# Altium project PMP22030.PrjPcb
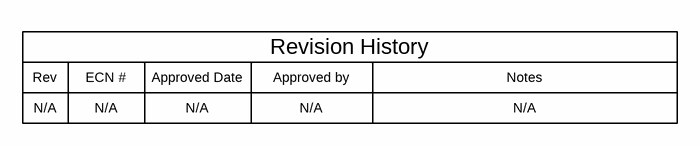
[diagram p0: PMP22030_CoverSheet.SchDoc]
CopyrightYear: 2019; PCB_Layout: Dee Lim; PCB_Rev: E1; PRJ_Customer: Public Release; PRJ_Engineer: Pradeep Shenoy; PRJ_Number: PMP22030; PRJ_Title: Automotive Infotainment Display; SCH_Rev: E1; TechSupport: http://www.ti.com/support; TID: N/A
4 sheets, 126 parts. Net scope: global (net labels, ports and power ports of the same name join across sheets).
Board file: PMP22030_PCB.PcbDoc
Sheets:
  PMP22030_CoverSheet.SchDoc
  PMP22030_Hardware.SchDoc
  PMP22030_3V3.SchDoc
  PMP22030_5V.SchDoc

## Sheet PMP22030_CoverSheet.SchDoc
size 431 x 279 mm; Date: Not shown in title block; ApprovedBy: Not shown in title block; CheckedBy: Not shown in title block; Author: Not shown in title block; CompanyName: Not shown in title block; Engineer: Not shown in title block; Organization: Not shown in title block; Address1: Not shown in title block; Address2: Not shown in title block; Address3: Not shown in title block; Address4: Not shown in title block; DocumentNumber: 1; Revision: Use project parameter SCH_Rev; SheetNumber: 1; SheetTotal: 4; PageSetup: Record=PageOptions¦CenterHorizontal=True¦CenterVertical=True¦PrintScale=1.00¦XCorrection=1.00¦YCorrection=1.00¦PrintKind=0¦BorderSize=5000000¦LeftOffset=0¦BottomOffset=0¦Orientation=2¦PaperLength=1000¦PaperWidth=1000¦Scale=100¦PaperSource=15¦PrintQuality=600¦MediaType=1¦DitherType=10¦PaperKind=Letter¦PrintScaleMode=1

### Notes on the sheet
- Rev
- N/A
- ECN #
- Approved Date
- Approved by
- Revision History
- Notes

## Sheet PMP22030_Hardware.SchDoc
size 431 x 279 mm; Date: Not shown in title block; ApprovedBy: Not shown in title block; CheckedBy: Not shown in title block; Author: Not shown in title block; CompanyName: Not shown in title block; Engineer: Not shown in title block; Organization: Not shown in title block; Address1: Not shown in title block; Address2: Not shown in title block; Address3: Not shown in title block; Address4: Not shown in title block; DocumentNumber: 4; Revision: Use project parameter SCH_Rev; SheetNumber: 4; SheetTotal: 4; PageSetup: Record=PageOptions¦CenterHorizontal=True¦CenterVertical=True¦PrintScale=1.00¦XCorrection=1.00¦YCorrection=1.00¦PrintKind=0¦BorderSize=5000000¦LeftOffset=0¦BottomOffset=0¦Orientation=2¦PaperLength=1000¦PaperWidth=1000¦Scale=100¦PaperSource=15¦PrintQuality=600¦MediaType=1¦DitherType=10¦PaperKind=Letter¦PrintScaleMode=1
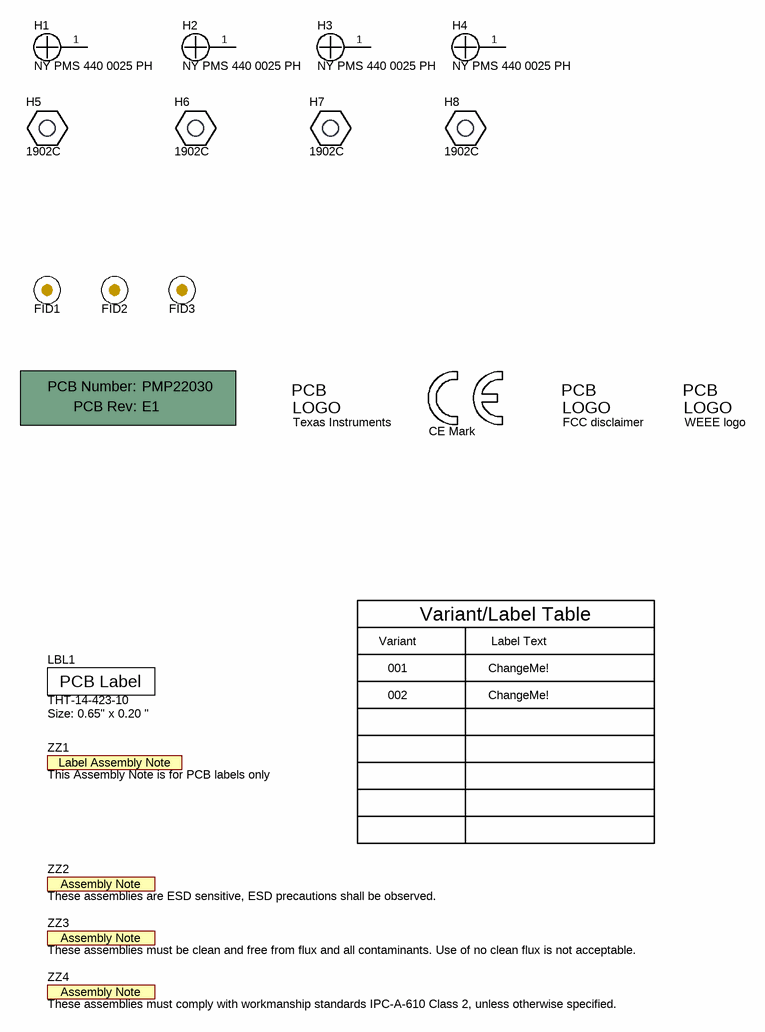
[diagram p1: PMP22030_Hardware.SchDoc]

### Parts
!PCB1  Printed Circuit Board  (value not drawn)  (mechanical)
FID1  Fiducial  [Fiducial10-20]  (value not drawn)
FID2  Fiducial  [Fiducial10-20]  (value not drawn)
FID3  Fiducial  [Fiducial10-20]  (value not drawn)
H1  NY PMS 440 0025 PH  [NY PMS 440 0025 PH]
H2  NY PMS 440 0025 PH  [NY PMS 440 0025 PH]
H3  NY PMS 440 0025 PH  [NY PMS 440 0025 PH]
H4  NY PMS 440 0025 PH  [NY PMS 440 0025 PH]
H5  1902C  [Keystone_1902C]
H6  1902C  [Keystone_1902C]
H7  1902C  [Keystone_1902C]
H8  1902C  [Keystone_1902C]
LBL1  THT-14-423-10  Note: Size: 0.65" x 0.20 "  [Label_650x200]
Logo1  CE Mark  [CE_Mark_5mm]  (no BOM)
Logo2  Texas Instruments  [TI_Stacked_Overlay_Small]  (no BOM)
Logo3  FCC disclaimer  [FCC_disclaimer]  (no BOM)
Logo4  WEEE logo  [WEEE_Minimum]  (no BOM)
ZZ1  This Assembly Note is for PCB labels only  [AssemblyNoteLabel]  (no BOM)
ZZ2  These assemblies are ESD sensitive, ESD precautions shall be observed.  [AssemblyNote]  (no BOM)
ZZ3  These assemblies must be clean and free from flux and all contaminants. Use of no clean flux is not acceptable.  [AssemblyNote]  (no BOM)
ZZ4  These assemblies must comply with workmanship standards IPC-A-610 Class 2, unless otherwise specified.  [AssemblyNote]  (no BOM)

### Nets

Not connected (* = marked no-connect by the designer): H1 1; H2 1; H3 1; H4 1

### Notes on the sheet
- Variant
- Variant/Label Table
- Label Text
- 001
- 002
- ChangeMe!

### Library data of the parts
!PCB1 = CMP-0003618-2: Manufacturer: Any; PartNumber: PMP22030
FID1-FID3 = CMP-0077181-1: Fiducial mark.  There is nothing to buy or mount.
H1-H4 = CMP-0003617-1: Machine Screw, Round, #4-40 x 1/4, Nylon, Philips panhead; Manufacturer: B&F Fastener Supply; CompType: Hardware
H5-H8 = CMP-0003610-1: Standoff, Hex, 0.5"L #4-40 Nylon; Manufacturer: Keystone; CompType: Hardware
LBL1 = CMP-0003625-1: Thermal Transfer Printable Labels, 0.650" W x 0.200" H - 10,000 per roll; Manufacturer: Brady; CompType: Label
Logo1 = CMP-0074844-1: SymbolCreator: a0412235
Logo2 = CMP-0074838-1: Texas Instrument Corporate Signature; SymbolCreator: a0412235; Lib Reference: TI_Logo; Library Reference: Logo
Logo3 = CMP-0074847-1: FCC_disclaimer; Library Reference: Logo
Logo4 = CMP-0074769-1
ZZ1 = CMP-0003616-3
ZZ2 = CMP-0077236-1
ZZ3 = CMP-0077237-1
ZZ4 = CMP-0077238-1

## Sheet PMP22030_3V3.SchDoc
size 431 x 279 mm; Date: Not shown in title block; ApprovedBy: Not shown in title block; CheckedBy: Not shown in title block; Author: Not shown in title block; CompanyName: Not shown in title block; Engineer: Not shown in title block; Organization: Not shown in title block; Address1: Not shown in title block; Address2: Not shown in title block; Address3: Not shown in title block; Address4: Not shown in title block; DocumentNumber: 3; Revision: Use project parameter SCH_Rev; SheetNumber: 3; SheetTotal: 4; PageSetup: Record=PageOptions¦CenterHorizontal=True¦CenterVertical=True¦PrintScale=1.00¦XCorrection=1.00¦YCorrection=1.00¦PrintKind=0¦BorderSize=5000000¦LeftOffset=0¦BottomOffset=0¦Orientation=2¦PaperLength=1000¦PaperWidth=1000¦Scale=100¦PaperSource=15¦PrintQuality=600¦MediaType=1¦DitherType=10¦PaperKind=Letter¦PrintScaleMode=1
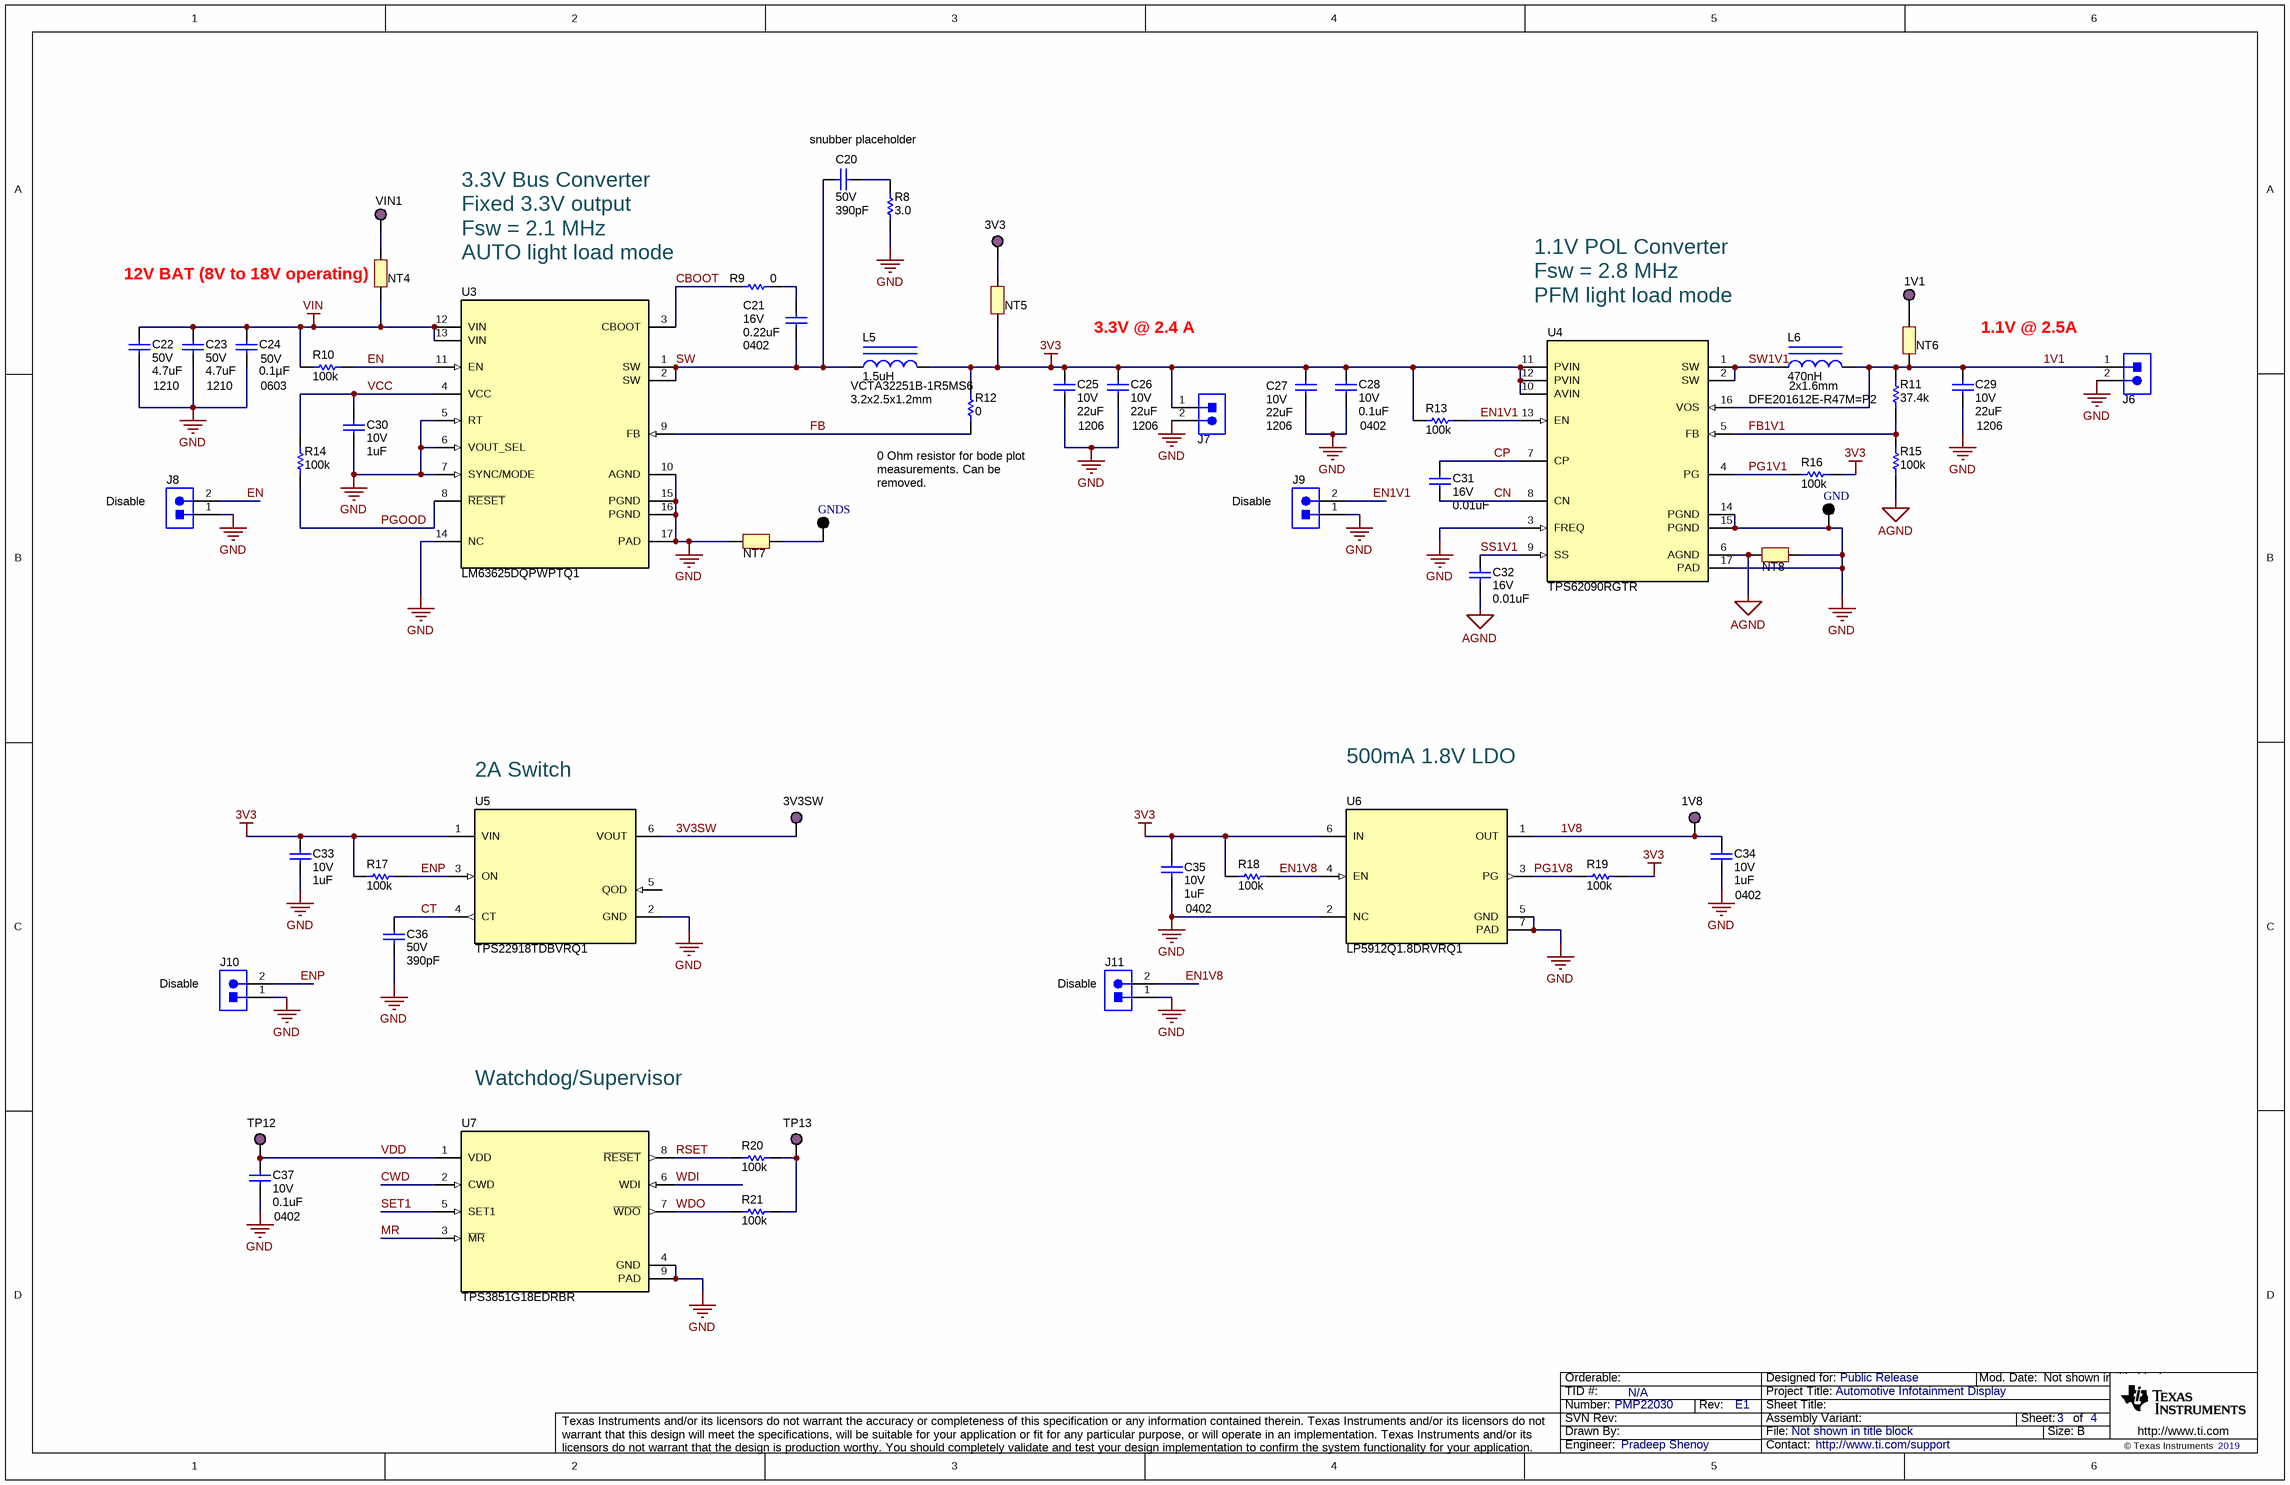
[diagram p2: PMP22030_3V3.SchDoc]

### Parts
1V1  5129  [Keystone5129]  (value not drawn)
1V8  5129  [Keystone5129]  (value not drawn)
3V3  5129  [Keystone5129]  (value not drawn)
3V3SW  5129  [Keystone5129]  (value not drawn)
C20  VDC_V: 50V  ValueDisplayed: 390pF  [0402S]  (hidden comment: GCM155R71H391KA37D)
C21  PackageReference: 0402  VDC_V: 16V  ValueDisplayed: 0.22uF  [0402S]  (hidden comment: C1005X7R1C224K050BC)
C22  PackageReference: 1210  VDC_V: 50V  ValueDisplayed: 4.7uF  [1210_280]  (hidden comment: CGA6P3X7R1H475K250AB)
C23  PackageReference: 1210  VDC_V: 50V  ValueDisplayed: 4.7uF  [1210_280]  (hidden comment: CGA6P3X7R1H475K250AB)
C24  Value2: 50V  ValueDisplayed: 0.1µF  [0603]  (hidden comment: CINHF)
C25  PackageReference: 1206  VDC_V: 10V  ValueDisplayed: 22uF  [1206_180]  (hidden comment: GCM31CR71A226KE02)
C26  PackageReference: 1206  VDC_V: 10V  ValueDisplayed: 22uF  [1206_180]  (hidden comment: GCM31CR71A226KE02)
C27  PackageReference: 1206  VDC_V: 10V  ValueDisplayed: 22uF  [1206_180]  (hidden comment: GCM31CR71A226KE02)
C28  VDC_V: 10V  ValueDisplayed: 0.1uF  [0402]  (hidden comment: GCM155R71A104KA55D)
C29  PackageReference: 1206  VDC_V: 10V  ValueDisplayed: 22uF  [1206_180]  (hidden comment: GCM31CR71A226KE02)
C30  VDC_V: 10V  ValueDisplayed: 1uF  [0402_070]  (hidden comment: GCM155C71A105KE38D)
C31  VDC_V: 16V  ValueDisplayed: 0.01uF  [0402S]  (hidden comment: GRM155R71C103KA01D)
C32  VDC_V: 16V  ValueDisplayed: 0.01uF  [0402S]  (hidden comment: GRM155R71C103KA01D)
C33  VDC_V: 10V  ValueDisplayed: 1uF  [0402_070]  (hidden comment: GCM155C71A105KE38D)
C34  PackageReference: 0402  VDC_V: 10V  ValueDisplayed: 1uF  [0402_070]  (hidden comment: GCM155C71A105KE38D)
C35  PackageReference: 0402  VDC_V: 10V  ValueDisplayed: 1uF  [0402_070]  (hidden comment: GCM155C71A105KE38D)
C36  VDC_V: 50V  ValueDisplayed: 390pF  [0402]  (hidden comment: GCM155R71H391KA37D)
C37  VDC_V: 10V  ValueDisplayed: 0.1uF  [0402]  (hidden comment: GCM155R71A104KA55D)
GND  5011  [Keystone5011]  (value not drawn)
GNDS  5011  [Keystone5011]  (value not drawn)
J6  PEC02SAAN  [CONN_PEC02SAAN]  (value not drawn)
J7  PEC02SAAN  [CONN_PEC02SAAN]  (value not drawn)
J8  PEC02SAAN  [CONN_PEC02SAAN]  (value not drawn)
J9  PEC02SAAN  [CONN_PEC02SAAN]  (value not drawn)
J10  PEC02SAAN  [CONN_PEC02SAAN]  (value not drawn)
J11  PEC02SAAN  [CONN_PEC02SAAN]  (value not drawn)
L5  PackageReference: 3.2x2.5x1.2mm  ValueDisplayed: 1.5uH  [VCTA32251B]  (hidden comment: VCTA32251B-1R5MS6)
L6  DFE201612E-R47M=P2  PackageReference: 2x1.6mm  ValueDisplayed: 470nH  [DFE201612E]
NT4  Net-Tie  [Net-Tie_10mil]  (value not drawn)  (net tie, no BOM)
NT5  Net-Tie  [Net-Tie_10mil]  (value not drawn)  (net tie, no BOM)
NT6  Net-Tie  [Net-Tie_10mil]  (value not drawn)  (net tie, no BOM)
NT7  Net-Tie  [Net-Tie_10mil]  (value not drawn)  (net tie, no BOM)
NT8  Net-Tie  [Net-Tie_10mil]  (value not drawn)  (net tie, no BOM)
R8  ValueDisplayed: 3.0  [0805]  (hidden comment: ERJ-6GEYJ3R0V)
R9  ValueDisplayed: 0  [0402S]  (hidden comment: CRCW04020000Z0EDHP)
R10  ValueDisplayed: 100k  [0402]  (hidden comment: RMCF0402FT100K)
R11  ValueDisplayed: 37.4k  [0402S]  (hidden comment: CRCW040237K4FKED)
R12  ValueDisplayed: 0  [0402]  (hidden comment: CRCW04020000Z0EDHP)
R13  ValueDisplayed: 100k  [0402]  (hidden comment: RMCF0402FT100K)
R14  ValueDisplayed: 100k  [0402]  (hidden comment: RMCF0402FT100K)
R15  ValueDisplayed: 100k  [0402S]  (hidden comment: CRCW0402100KFKED)
R16  ValueDisplayed: 100k  [0402]  (hidden comment: RMCF0402FT100K)
R17  ValueDisplayed: 100k  [0402]  (hidden comment: RMCF0402FT100K)
R18  ValueDisplayed: 100k  [0402]  (hidden comment: RMCF0402FT100K)
R19  ValueDisplayed: 100k  [0402]  (hidden comment: RMCF0402FT100K)
R20  ValueDisplayed: 100k  [0402]  (hidden comment: RMCF0402FT100K)
R21  ValueDisplayed: 100k  [0402]  (hidden comment: RMCF0402FT100K)
TP12  5129  [Keystone5129]  (value not drawn)
TP13  5129  [Keystone5129]  (value not drawn)
U3  LM63625DQPWPTQ1  [PWP0016K_N]
U4  TPS62090RGTR  [RGT0016C]
U5  TPS22918TDBVRQ1  [DBV0006A_N]
U6  LP5912Q1.8DRVRQ1  [DRV0006A]
U7  TPS3851G18EDRBR  [DRB0008A]
VIN1  5129  [Keystone5129]  (value not drawn)

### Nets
3V3: C25.1 C26.1 C27.1 C28.1 C33.1 C35.1 J7.1 L5.2 NT5.1 R12.1 R13.1 R16.2 R17.1 R18.1 R19.2 U4.10(AVIN) U4.11(PVIN) U4.12(PVIN) U5.1(VIN) U6.6(IN)
AGND: C32.2 NT8.2 R15.1 U4.6(AGND)
GND: C22.2 C23.2 C24.2 C25.2 C26.2 C27.2 C28.2 C29.2 C30.2 C33.2 C34.2 C35.2 C36.1 C37.2 GND.1 J6.2 J7.2 J8.1 J9.1 J10.1 J11.1 NT7.2 NT8.1 R8.1 U3.5(RT) U3.6(VOUT_SEL) U3.7(SYNC/MODE) U3.10(AGND) U3.14(NC) U3.15(PGND) U3.16(PGND) U3.17(PAD) U4.3(FREQ) U4.14(PGND) U4.15(PGND) U4.17(PAD) U5.2(GND) U6.2(NC) U6.5(GND) U6.7(PAD) U7.4(GND) U7.9(PAD)
VIN: C22.1 C23.1 C24.1 NT4.1 R10.1 U3.12(VIN) U3.13(VIN)
1V1: C29.1 J6.1 L6.2 NT6.1 R11.2 U4.16(VOS)
1V8: 1V8.1 C34.1 U6.1(OUT)
3V3SW: 3V3SW.1 U5.6(VOUT)
CBOOT: R9.2 U3.3(CBOOT)
CN: C31.2 U4.8(CN)
CP: C31.1 U4.7(CP)
CT: C36.2 U5.4(CT)
CWD: U7.2(CWD)
EN: J8.2 R10.2 U3.11(EN)
EN1V1: J9.2 R13.2 U4.13(EN)
EN1V8: J11.2 R18.2 U6.4(EN)
ENP: J10.2 R17.2 U5.3(ON)
FB: R12.2 U3.9(FB)
FB1V1: R11.1 R15.2 U4.5(FB)
MR: U7.3(~{MR})
PG1V1: R16.1 U4.4(PG)
PG1V8: R19.1 U6.3(PG)
PGOOD: R14.2 U3.8(~{RESET})
RSET: R20.1 U7.8(~{RESET})
SET1: U7.5(SET1)
SS1V1: C32.1 U4.9(SS)
SW: C20.2 C21.2 L5.1 U3.1(SW) U3.2(SW)
SW1V1: L6.1 U4.1(SW) U4.2(SW)
VCC: C30.1 R14.1 U3.4(VCC)
VDD: C37.1 TP12.1 U7.1(VDD)
WDI: U7.6(WDI)
WDO: R21.1 U7.7(~{WDO})
Net1V1_1: 1V1.1 NT6.2
Net3V3_1: 3V3.1 NT5.2
NetC20_1: C20.1 R8.2
NetC21_1: C21.1 R9.1
NetGNDS_1: GNDS.1 NT7.1
NetNT4_2: NT4.2 VIN1.1
NetR20_2: R20.2 R21.2 TP13.1

Not connected (* = marked no-connect by the designer): U5 5(QOD)

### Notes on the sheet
- snubber placeholder
- (near NT4) 12V BAT (8V to 18V operating)
- 3.3V Bus Converter
  Fixed 3.3V output
  Fsw = 2.1 MHz
  AUTO light load mode
- 3.3V @ 2.4 A
- 1.1V POL Converter
  Fsw = 2.8 MHz
  PFM light load mode
- 1.1V @ 2.5A
- (near J8) Disable
- (near R12) 0 Ohm resistor for bode plot measurements. Can be removed.
- (near J9) Disable
- (near U5) 2A Switch
- 500mA 1.8V LDO
- (near J10) Disable
- (near J11) Disable
- Watchdog/Supervisor

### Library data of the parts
1V1 1V8 3V3 3V3SW TP12 TP13 VIN1 = CMP-0055160-1: Test Point, Multipurpose, Purple, TH; Manufacturer: Keystone; CNHeader: FALSE; ContactFinish: Silver; CT: TRUE
C20 = CMP-0080703-2: CAP, CERM, 390 pF, 50 V,+/- 10%, X7R, AEC-Q200 Grade 1, 0402; Manufacturer: MuRata; Cap_Case: 0402; SizeX_mm: 1; SizeZ_mm: 0.6; SizeY_mm: 0.5; AEC Qualified: Y; Value: 390pF; Polarized: N; AEC Category: Q200; TaMax_C: 125°C; TaMin_C: -55°C; SizeAreaWB_mm2: 3; U/M: EA
C21 = CMP-0006293-1: CAP, CERM, 0.22 uF, 16 V, +/- 10%, X7R, 0402; Manufacturer: TDK; TaMin_C: -55°C; Polarized: N; SizeAreaWB_mm2: 3; Value1: Unknown; U/M: EA; Value: 0.22uF; TaMax_C: 125°C; SizeZ_mm: 0.6; SizeX_mm: 1; SizeY_mm: 0.5; Cap_F: 220nF; AEC Category: Q200
C22 C23 = CMP-0009162-2: CAP, CERM, 4.7 uF, 50 V, +/- 10%, X7R, AEC-Q200 Grade 1, 1210; Manufacturer: TDK; TaMin_C: -55°C; ESR_ohm: 3.166m; Polarized: N; SizeAreaWB_mm2: 14.7; Value1: 0.003166 ohm; U/M: EA; Value: 4.7uF; TaMax_C: 125°C; SizeZ_mm: 2.8; SizeX_mm: 3.2; SizeY_mm: 2.5; SizeArea_mm2: 8; AEC Qualified: Y; Cap_F: 4.7µF; IRMS_A: 4.13311A; AEC Grade: 1; AEC Category: Q200
C24 = CMP-0079602-1: CAP, CERM, 0.1 µF, 50 V,+/- 10%, X7R, AEC-Q200 Grade 1, 0603; Manufacturer: Kemet; PartNumber: C0603C104K5RACAUTO; TaMin_C: -55°C; Polarized: N; SizeAreaWB_mm2: 4.68; U/M: EA; Value: 0.1uF; TaMax_C: 125°C; SizeZ_mm: 1; SizeX_mm: 1.6; SizeY_mm: 0.8; SizeArea_mm2: 1.28; CompType: Capacitor; AEC Qualified: Y; Cap_F: 100nF; AEC Category: Q200
C25-C27 C29 = CMP-0008811-1: CAP, CERM, 22 uF, 10 V, +/- 10%, X7R, AEC-Q200 Grade 1, 1206; Manufacturer: MuRata; TaMin_C: -55°C; Polarized: N; SizeAreaWB_mm2: 10.92; Value1: Unknown; U/M: EA; Value: 22uF; TaMax_C: 125°C; SizeZ_mm: 1.8; SizeX_mm: 3.2; SizeY_mm: 1.6; SizeArea_mm2: 5.12; AEC Qualified: Y; Cap_F: 22µF; AEC Grade: 1; AEC Category: Q200
C28 C37 = CMP-0006350-2: CAP, CERM, 0.1 uF, 10 V, +/- 10%, X7R, AEC-Q200 Grade 1, 0402; Manufacturer: MuRata; TaMin_C: -55°C; Polarized: N; SizeAreaWB_mm2: 3; Value1: Unknown; U/M: EA; Value: 0.1uF; TaMax_C: 125°C; SizeZ_mm: 0.6; SizeX_mm: 1; SizeY_mm: 0.5; AEC Qualified: Y; Cap_F: 100nF; AEC Category: Q200
C30 C33 = CMP-0006349-1: CAP, CERM, 1 uF, 10 V, +/- 10%, X7S, AEC-Q200 Grade 1, 0402; Manufacturer: MuRata; TaMin_C: -55°C; Polarized: N; SizeAreaWB_mm2: 3; Value1: Unknown; U/M: EA; Value: 1uF; TaMax_C: 125°C; SizeZ_mm: 0.7; SizeX_mm: 1; SizeY_mm: 0.5; Cap_Case: 0402; AEC Qualified: Y; Cap_F: 1µF; AEC Category: Q200
C31 C32 = CMP-0006639-2: CAP, CERM, 0.01 uF, 16 V, +/- 10%, X7R, 0402; Manufacturer: MuRata; TaMin_C: -55°C; Polarized: N; SizeAreaWB_mm2: 3; Value1: Unknown; U/M: EA; Value: 0.01uF; TaMax_C: 125°C; SizeZ_mm: 0.6; SizeX_mm: 1; SizeY_mm: 0.5; Cap_Case: 0402; Cap_F: 10nF; AEC Category: Q200
C34 C35 = CMP-0006349-1: CAP, CERM, 1 uF, 10 V, +/- 10%, X7S, AEC-Q200 Grade 1, 0402; Manufacturer: MuRata; TaMin_C: -55°C; Polarized: N; SizeAreaWB_mm2: 3; Value1: Unknown; U/M: EA; Value: 1uF; TaMax_C: 125°C; SizeZ_mm: 0.7; SizeX_mm: 1; SizeY_mm: 0.5; AEC Qualified: Y; Cap_F: 1µF; AEC Category: Q200
C36 = CMP-0080703-2: CAP, CERM, 390 pF, 50 V,+/- 10%, X7R, AEC-Q200 Grade 1, 0402; Manufacturer: MuRata; SizeX_mm: 1; SizeZ_mm: 0.6; SizeY_mm: 0.5; AEC Qualified: Y; Value: 390pF; Polarized: N; AEC Category: Q200; TaMax_C: 125°C; TaMin_C: -55°C; SizeAreaWB_mm2: 3; U/M: EA
GND GNDS = CMP-0055148-1: Test Point, Multipurpose, Black, TH; Manufacturer: Keystone; CNHeader: FALSE; Green_Lifecycle: Active; Green_REACh: Passed; ContactFinish: Silver; CT: TRUE
J6-J11 = CMP-0002337-1: Header, 100mil, 2x1, Tin, TH; Manufacturer: Sullins Connector Solutions; CNHeader: TRUE; Current_A: 3A; Green_Lifecycle: Not Set; Shrouded: N; Gender: Male; Green_REACh: Incomplete; Voltage_V: 1.8kV; Row_Count: 1; Pitch_mm: 2.54; CT: FALSE; Cert_UL: Y
L5 = CMP-0059972-1: Inductor, 1.5 uH, 3.1 A, 0.054 ohm, SMD; Manufacturer: Cyntec; Isat: 3.7A @ 30% inductance drop; Irms: 3.1A @ 40C rise; SizeAreaWB_mm2: 14.7; DCR_ohm: 0.054; Value: 1.5uH; Imax_A: 3.1A; SizeZ_mm: 1.2; SizeX_mm: 3.2; SizeY_mm: 2.5; SizeArea_mm2: 8; Ind_H: 1.5µH; AEC Qualified: N; AEC Category: Q200
L6 = CMP-0080779-1: Inductor, Shielded, Metal Composite, 470 nH, 4.5 A, 0.026 ohm, SMD; Manufacturer: MuRata; Isat: 5.5A @ 30% inductance drop; Irms: 4.5A @ 40C rise; SizeAreaWB_mm2: 7.8; DCR_ohm: 0.026; Value: 470nH; Imax_A: 4.5A; SizeZ_mm: 1.2; SizeX_mm: 2; SizeY_mm: 1.6; SizeArea_mm2: 3.2; AEC Qualified: N; AEC Category: Q200
NT4-NT8 = CMP-0078142-1: Single point connection between nets.
R8 = CMP-0020720-3: RES, 3.0, 5%, 0.125 W, AEC-Q200 Grade 0, 0805; Manufacturer: Panasonic; Power_W: 125mW; TempCo: 600 ppm/C; Value_Code: 3R00; Value: 3.0; EIA_Code: E24; Res_ohm: 3; SizeX_mm: 2; SizeY_mm: 1.25; SizeZ_mm: 1.45; Value2: 0.125W; SizeArea_mm2: 2.5; AEC Qualified: Y; VDC_V: 150V; AEC Category: Q200; AEC Grade: 0; SizeAreaWB_mm2: 6.75
R9 R12 = CMP-0081856-1: RES, 0, 0%, 0.2 W, AEC-Q200 Grade 0, 0402; Manufacturer: Vishay-Dale; SizeAreaWB_mm2: 3; SizeArea_mm2: 0.5; AEC Qualified: Y; AEC Category: Q200; Value: 0; SizeZ_mm: 0.6; Power_W: 200mW; VDC_V: 50V; Value2: 0.2W; SizeX_mm: 1
R10 R13 R14 R16-R21 = CMP-0026753-1: RES, 100 k, 1%, 0.063 W, AEC-Q200 Grade 0, 0402; Manufacturer: Stackpole Electronics Inc; Power_W: 63mW; TempCo: 100 ppm/C; U/M: EA; Value: 100k; EIA_Code: E96; SizeX_mm: 1; SizeY_mm: 0.5; SizeZ_mm: 0.6; Value2: 0.063W; AEC Qualified: Y; VDC_V: 50V; AEC Grade: 0; AEC Category: Q200
R11 = CMP-0026319-2: RES, 37.4 k, 1%, 0.063 W, AEC-Q200 Grade 0, 0402; Manufacturer: Vishay-Dale; Power_W: 63mW; TempCo: 100 ppm/C; Value_Code: 37k4; Value: 37.4k; EIA_Code: E96; SizeX_mm: 1; SizeY_mm: 0.5; SizeZ_mm: 0.6; Value2: 0.063W; AEC Qualified: Y; VDC_V: 50V; AEC Category: Q200; AEC Grade: 0
R15 = CMP-0025950-3: RES, 100 k, 1%, 0.063 W, AEC-Q200 Grade 0, 0402; Manufacturer: Vishay-Dale; Power_W: 63mW; TempCo: 100 ppm/C; Value: 100k; EIA_Code: E96; SizeX_mm: 1; SizeY_mm: 0.5; SizeZ_mm: 0.6; Value2: 0.063W; AEC Qualified: Y; VDC_V: 50V; AEC Category: Q200; AEC Grade: 0
U3 = CMP-0080080-4: 3.5-V to 36-V, 2.5-A Synchronous Step-Down Voltage Regulator with Spread Spectrum, PWP0016D (TSSOP-16); Alternate Manufacturer: Texas Instruments; SizeAreaWB_mm2: 58.8; SizeZ_mm: 1.2; SizeX_mm: 6.4; SizeY_mm: 5; SizeArea_mm2: 32; CompType: IC; AEC Qualified: Y; AEC Category: Q200; Rating: Automotive
U4 = CMP-0067085-2: 3A, 6V input, up to 97% efficiency, Synchronous Step Down Converter with DCS(TM) Control, RGT0016C (VQFN-16); Manufacturer: Texas Instruments; Alternate PartNumber: TPS62090RGTT; SizeX_mm: 4.0; CompType: IC; SizeZ_mm: 1.0; SizeArea_mm2: 16.0; SizeAreaWB_mm2: 25.0; U/M: EA; Green_Lifecycle: Active; Green_REACh: Passed
U5 = CMP-0081996-1: 5.5V, 2A, 52mΩ Automotive High-Side Load Switch with Adjustable Rise Time & Quick Output Discharge, DBV0006A (SOT-23-6); Alternate PartNumber: TPS22918TDBVTQ1; Alternate Manufacturer: Texas Instruments; SizeAreaWB_mm2: 14.82; SizeZ_mm: 1.45; SizeX_mm: 2.8; SizeY_mm: 2.9; SizeArea_mm2: 8.12; CompType: IC; AEC Qualified: Y; AEC Category: Q200
U6 = CMP-0076265-4: Automotive 500-mA Low-Noise, Low-IQ LDO, DRV0006A (WSON-6); Manufacturer: Texas Instruments; Alternate PartNumber: LP5912Q1.8DRVTQ1; SizeX_mm: 2; CompType: IC; SizeZ_mm: 0.8; SizeArea_mm2: 4; SizeAreaWB_mm2: 9; U/M: EA
U7 = CMP-0013379-4: High-Accuracy Voltage Supervisor With Integrated Watchdog Timer, DRB0008A (VSON-8); Alternate Manufacturer: Texas Instruments; Alternate PartNumber: TPS3851G18EDRBT; SizeAreaWB_mm2: 16.0; SizeX_mm: 3.0; AEC Category: Q200; SizeArea_mm2: 9.0; CompType: IC; AEC Qualified: N; SizeZ_mm: 1.0; Rating: Catalog

## Sheet PMP22030_5V.SchDoc
size 431 x 279 mm; Date: Not shown in title block; ApprovedBy: Not shown in title block; CheckedBy: Not shown in title block; Author: Not shown in title block; CompanyName: Not shown in title block; Engineer: Not shown in title block; Organization: Not shown in title block; Address1: Not shown in title block; Address2: Not shown in title block; Address3: Not shown in title block; Address4: Not shown in title block; DocumentNumber: 2; Revision: Use project parameter SCH_Rev; SheetNumber: 2; SheetTotal: 4; PageSetup: Record=PageOptions¦CenterHorizontal=True¦CenterVertical=True¦PrintScale=1.00¦XCorrection=1.00¦YCorrection=1.00¦PrintKind=0¦BorderSize=5000000¦LeftOffset=0¦BottomOffset=0¦Orientation=2¦PaperLength=1000¦PaperWidth=1000¦Scale=100¦PaperSource=15¦PrintQuality=600¦MediaType=1¦DitherType=10¦PaperKind=Letter¦PrintScaleMode=1
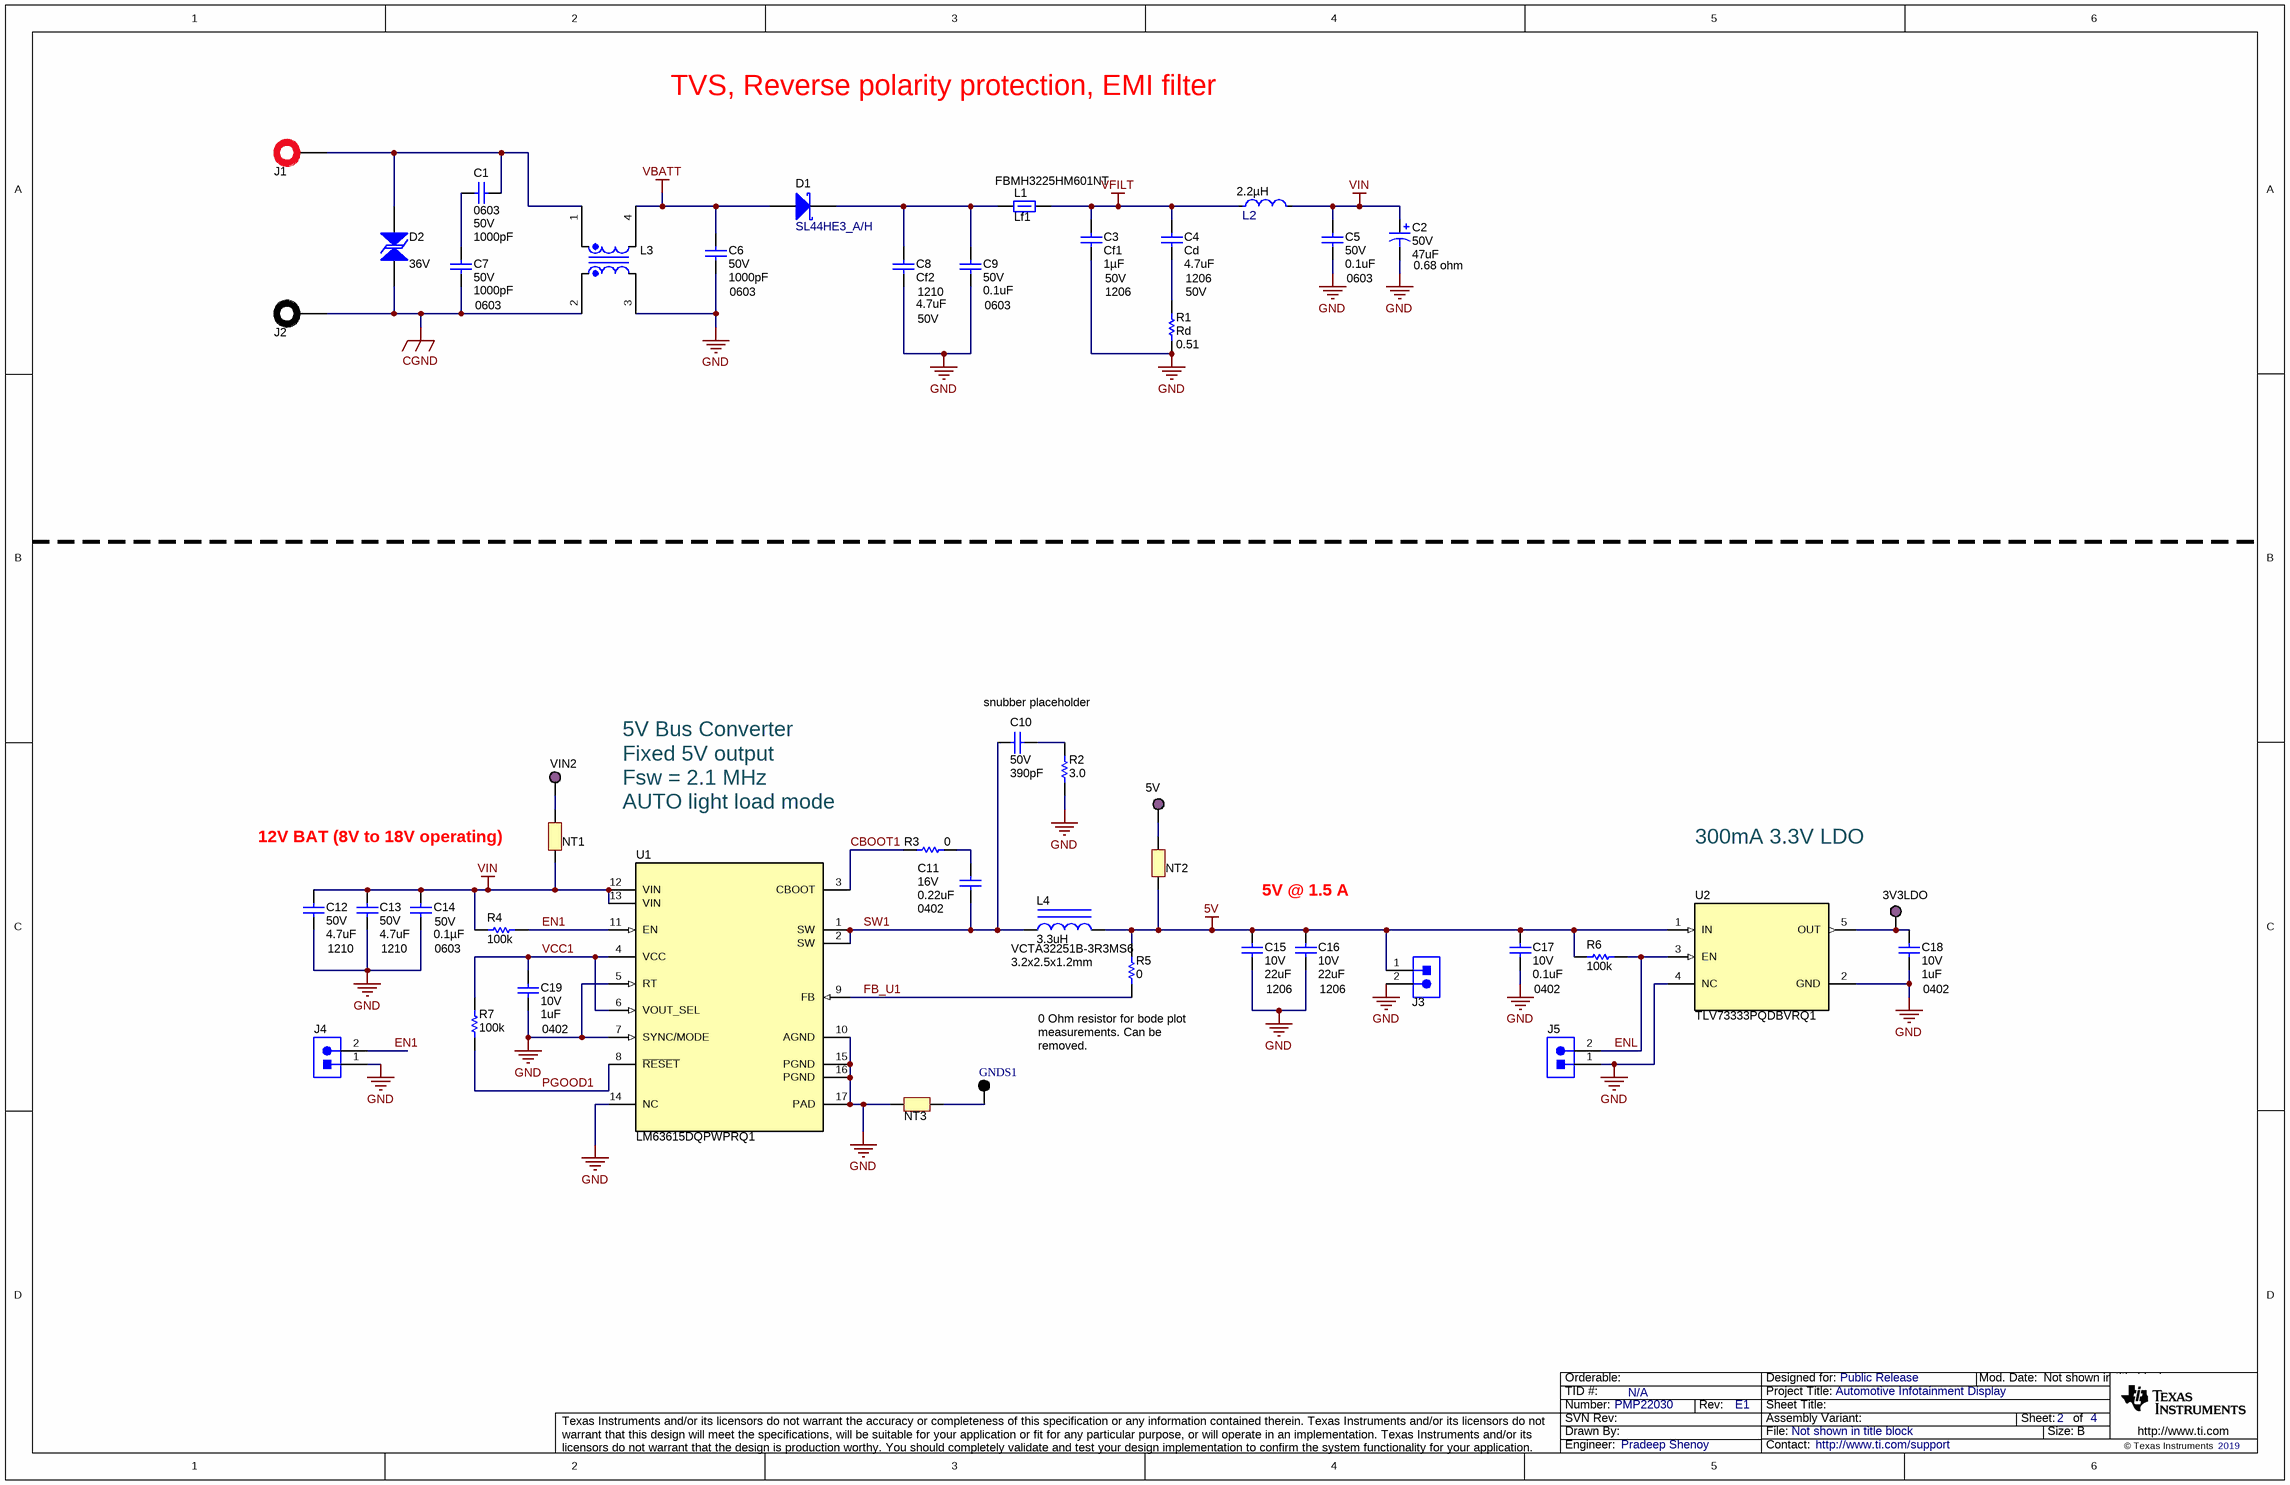
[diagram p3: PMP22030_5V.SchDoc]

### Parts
3V3LDO  5129  [Keystone5129]  (value not drawn)
5V  5129  [Keystone5129]  (value not drawn)
C1  VDC_V: 50V  ValueDisplayed: 1000pF  [0603]  (hidden comment: C0603C102J5RACAUTO)
C2  Value1: 0.68 ohm  VDC_V: 50V  ValueDisplayed: 47uF  [Panasonic_D]  (hidden comment: EEEFT1H470AP)
C3  Cf1  PackageReference: 1206  VDC_V: 50V  ValueDisplayed: 1µF  [1206_180]
C4  Cd  PackageReference: 1206  VDC_V: 50V  ValueDisplayed: 4.7uF  [1206_180]
C5  VDC_V: 50V  ValueDisplayed: 0.1uF  [0603]  (hidden comment: GRM188R71H104KA93D)
C6  VDC_V: 50V  ValueDisplayed: 1000pF  [0603]  (hidden comment: C0603C102J5RACAUTO)
C7  VDC_V: 50V  ValueDisplayed: 1000pF  [0603]  (hidden comment: C0603C102J5RACAUTO)
C8  Cf2  PackageReference: 1210  VDC_V: 50V  ValueDisplayed: 4.7uF  [1210_280]
C9  VDC_V: 50V  ValueDisplayed: 0.1uF  [0603]  (hidden comment: GRM188R71H104KA93D)
C10  VDC_V: 50V  ValueDisplayed: 390pF  [0402S]  (hidden comment: GCM155R71H391KA37D)
C11  PackageReference: 0402  VDC_V: 16V  ValueDisplayed: 0.22uF  [0402S]  (hidden comment: C1005X7R1C224K050BC)
C12  PackageReference: 1210  VDC_V: 50V  ValueDisplayed: 4.7uF  [1210_280]  (hidden comment: CGA6P3X7R1H475K250AB)
C13  PackageReference: 1210  VDC_V: 50V  ValueDisplayed: 4.7uF  [1210_280]  (hidden comment: CGA6P3X7R1H475K250AB)
C14  Value2: 50V  ValueDisplayed: 0.1µF  [0603]  (hidden comment: CINHF)
C15  PackageReference: 1206  VDC_V: 10V  ValueDisplayed: 22uF  [1206_180]  (hidden comment: GCM31CR71A226KE02)
C16  PackageReference: 1206  VDC_V: 10V  ValueDisplayed: 22uF  [1206_180]  (hidden comment: GCM31CR71A226KE02)
C17  VDC_V: 10V  ValueDisplayed: 0.1uF  [0402]  (hidden comment: GCM155R71A104KA55D)
C18  PackageReference: 0402  VDC_V: 10V  ValueDisplayed: 1uF  [0402_070]  (hidden comment: GCM155C71A105KE38D)
C19  PackageReference: 0402  VDC_V: 10V  ValueDisplayed: 1uF  [0402_070]  (hidden comment: GCM155C71A105KE38D)
D1  SL44HE3_A/H  [SMC]
D2  value 36V  [SMB-Bi]  (hidden comment: SM6T42CAY)
GNDS1  5011  [Keystone5011]  (value not drawn)
J1  6091  [6091]  (value not drawn)
J2  6092  [6092]  (value not drawn)
J3  PEC02SAAN  [CONN_PEC02SAAN]  (value not drawn)
J4  PEC02SAAN  [CONN_PEC02SAAN]  (value not drawn)
J5  PEC02SAAN  [CONN_PEC02SAAN]  (value not drawn)
L1  Lf1  PartNumber: FBMH3225HM601NT  [1210_280]
L2  Ind_H: 2.2µH  [FP-78438336022_SMD2-MFG]  (hidden comment: 78438336022)
L3  744273102  [WE-SL5_HC]  (value not drawn)
L4  PackageReference: 3.2x2.5x1.2mm  ValueDisplayed: 3.3uH  [VCTA32251B]  (hidden comment: VCTA32251B-3R3MS6)
NT1  Net-Tie  [Net-Tie_10mil]  (value not drawn)  (net tie, no BOM)
NT2  Net-Tie  [Net-Tie_10mil]  (value not drawn)  (net tie, no BOM)
NT3  Net-Tie  [Net-Tie_10mil]  (value not drawn)  (net tie, no BOM)
R1  Rd  ValueDisplayed: 0.51  [0603]
R2  ValueDisplayed: 3.0  [0805]  (hidden comment: ERJ-6GEYJ3R0V)
R3  ValueDisplayed: 0  [0402S]  (hidden comment: CRCW04020000Z0EDHP)
R4  ValueDisplayed: 100k  [0402]  (hidden comment: RMCF0402FT100K)
R5  ValueDisplayed: 0  [0402]  (hidden comment: CRCW04020000Z0EDHP)
R6  ValueDisplayed: 100k  [0402]  (hidden comment: RMCF0402FT100K)
R7  ValueDisplayed: 100k  [0402]  (hidden comment: RMCF0402FT100K)
U1  LM63615DQPWPRQ1  [PWP0016K_N]
U2  TLV73333PQDBVRQ1  [DBV0005A_N]
VIN2  5129  [Keystone5129]  (value not drawn)

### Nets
5V: C15.1 C16.1 C17.1 J3.1 L4.2 NT2.1 R5.1 R6.1 U2.1(IN)
CGND: C7.1 D2.1 J2.1 L3.2
GND: C2.2(-) C3.2 C5.2 C6.1 C8.2 C9.2 C12.2 C13.2 C14.2 C15.2 C16.2 C17.2 C18.2 C19.2 J3.2 J4.1 J5.1 L3.3 NT3.2 R1.1 R2.1 U1.5(RT) U1.7(SYNC/MODE) U1.10(AGND) U1.14(NC) U1.15(PGND) U1.16(PGND) U1.17(PAD) U2.2(GND) U2.4(NC)
VBATT: C6.2 D1.2(A) L3.4
VFILT: C3.1 C4.1 L1.2 L2.1
VIN: C2.1(+) C5.1 C12.1 C13.1 C14.1 L2.2 NT1.1 R4.1 U1.12(VIN) U1.13(VIN)
CBOOT1: R3.2 U1.3(CBOOT)
EN1: J4.2 R4.2 U1.11(EN)
ENL: J5.2 R6.2 U2.3(EN)
FB_U1: R5.2 U1.9(FB)
PGOOD1: R7.2 U1.8(~{RESET})
SW1: C10.2 C11.2 L4.1 U1.1(SW) U1.2(SW)
VCC1: C19.1 R7.1 U1.4(VCC) U1.6(VOUT_SEL)
Net3V3LDO_1: 3V3LDO.1 C18.1 U2.5(OUT)
Net5V_1: 5V.1 NT2.2
NetC1_1: C1.1 D2.2 J1.1 L3.1
NetC1_2: C1.2 C7.2
NetC4_2: C4.2 R1.2
NetC8_1: C8.1 C9.1 D1.1(K) L1.1
NetC10_1: C10.1 R2.2
NetC11_1: C11.1 R3.1
NetGNDS1_1: GNDS1.1 NT3.1
NetNT1_2: NT1.2 VIN2.1

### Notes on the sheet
- TVS, Reverse polarity protection, EMI filter
- snubber placeholder
- 12V BAT (8V to 18V operating)
- (near R3) 5V Bus Converter
  Fixed 5V output
  Fsw = 2.1 MHz
  AUTO light load mode
- 5V @ 1.5 A
- 300mA 3.3V LDO
- (near R5) 0 Ohm resistor for bode plot measurements. Can be removed.

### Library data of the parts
3V3LDO 5V VIN2 = CMP-0055160-1: as 1V1 on sheet PMP22030_3V3
C1 C6 C7 = CMP-0006844-4: CAP, CERM, 1000 pF, 50 V, +/- 5%, X7R, AEC-Q200 Grade 1, 0603; Manufacturer: Kemet; TaMin_C: -55°C; Polarized: N; SizeAreaWB_mm2: 4.68; Value1: Unknown; U/M: EA; Value: 1000pF; TaMax_C: 125°C; SizeZ_mm: 1; SizeX_mm: 1.6; SizeY_mm: 0.8; SizeArea_mm2: 1.28; AEC Qualified: Y; Cap_F: 1nF; AEC Category: Q200
C2 = CMP-0011204-2: CAP, AL, 47 uF, 50 V, +/- 20%, 0.68 ohm, AEC-Q200 Grade 2, SMD; Manufacturer: Panasonic; TaMin_C: -55°C; ESR_ohm: 0.68; Polarized: Y; SizeAreaWB_mm2: 73.96; U/M: EA; Value: 47uF; TaMax_C: 105°C; SizeZ_mm: 6.1; SizeX_mm: 6.6; Cap_Case: 6.3x5.8mm; SizeArea_mm2: 43.56; CompType: Capacitor; Cap_F: 47µF; IRMS_A: 195mA; AEC Grade: 2; AEC Category: Q200
C3 = CMP-0080106-1: CAP, CERM, 1 µF, 50 V,+/- 10%, X7R, AEC-Q200 Grade 1, 1206; PartNumber: UMK316B7105KLHT; Manufacturer: Taiyo Yuden; SizeAreaWB_mm2: 10.92; SizeArea_mm2: 5.12; AEC Qualified: Y; AEC Category: Q200; Value: 1uF; TaMax_C: 125°C; SizeZ_mm: 1.8; AEC Grade: 1; Polarized: N; TaMin_C: -55°C; SizeY_mm: 1.6; U/M: EA; CompType: Capacitor; SizeX_mm: 3.2
C4 = CMP-0008702-2: CAP, CERM, 4.7 uF, 50 V, +/- 10%, X7R, 1206; Manufacturer: TDK; PartNumber: C3216X7R1H475K160AC; TaMin_C: -55°C; ESR_ohm: 3.158m; Polarized: N; SizeAreaWB_mm2: 10.92; Value1: 0.003158 ohm; U/M: EA; Value: 4.7uF; TaMax_C: 125°C; SizeZ_mm: 1.8; SizeX_mm: 3.2; SizeY_mm: 1.6; SizeArea_mm2: 5.12; CompType: Capacitor; Cap_F: 4.7µF; IRMS_A: 4.08379A; AEC Category: Q200
C5 C9 = CMP-0007434-2: CAP, CERM, 0.1 uF, 50 V, +/- 10%, X7R, 0603; Manufacturer: MuRata; TaMin_C: -55°C; Polarized: N; SizeAreaWB_mm2: 4.68; Value1: Unknown; U/M: EA; Value: 0.1uF; TaMax_C: 125°C; SizeZ_mm: 1; SizeX_mm: 1.6; SizeY_mm: 0.8; SizeArea_mm2: 1.28; Cap_F: 100nF; AEC Category: Q200
C8 = CMP-0009163-2: CAP, CERM, 4.7 uF, 50 V, +/- 20%, X7R, AEC-Q200 Grade 1, 1210; Manufacturer: TDK; PartNumber: CGA6P3X7R1H475M250AB; TaMin_C: -55°C; Polarized: N; SizeAreaWB_mm2: 14.7; Value1: Unknown; U/M: EA; Value: 4.7uF; TaMax_C: 125°C; SizeZ_mm: 2.8; SizeX_mm: 3.2; SizeY_mm: 2.5; SizeArea_mm2: 8; CompType: Capacitor; AEC Qualified: Y; Cap_F: 4.7µF; AEC Grade: 1; AEC Category: Q200
C10 = CMP-0080703-2: as C20 on sheet PMP22030_3V3
C11 = CMP-0006293-1: as C21 on sheet PMP22030_3V3
C12 C13 = CMP-0009162-2: as C22 on sheet PMP22030_3V3
C14 = CMP-0079602-1: as C24 on sheet PMP22030_3V3
C15 C16 = CMP-0008811-1: as C25 on sheet PMP22030_3V3
C17 = CMP-0006350-2: as C28 on sheet PMP22030_3V3
C18 C19 = CMP-0006349-1: as C34 on sheet PMP22030_3V3
D1 = CMP-0028936-2: Diode, Schottky, 40 V, 4 A, AEC-Q101, SMC; Manufacturer: Vishay-Semiconductor; Value2: 0.44V; TJmax_C: 125°C; SizeZ_mm: 2.6; Vr_V: 40V; Value1: 4A; SizeArea_mm2: 50.5686; SizeX_mm: 8.13; SizeY_mm: 6.22; Vf_V: 440mV; Value: 40V; AEC Qualified: Y; AEC Category: Q101; Green_REACh: Incomplete; SizeAreaWB_mm2: 83.2686; Green_Lifecycle: Not Set
D2 = CMP-0006049-2: Diode, TVS, Bi, 36 V, 76 Vc, AEC-Q101, SMB; Manufacturer: STMicroelectronics; Value1: W; U/M: EA; AEC Qualified: Y; AEC Category: Q101
GNDS1 = CMP-0055148-1: as GND on sheet PMP22030_3V3
J1 = CMP-0055167-2: Standard Banana Jack, Insulated, Red; Manufacturer: Keystone; CT: TRUE; Green_REACh: Passed; CNHeader: FALSE; Green_Lifecycle: Active
J2 = CMP-0055168-2: Standard Banana Jack, Insulated, Black; Manufacturer: Keystone; CT: TRUE; Green_REACh: Passed; CNHeader: FALSE; Green_Lifecycle: Active
J3-J5 = CMP-0002337-1: as J6 on sheet PMP22030_3V3
L1 = CMP-0003374-1: Ferrite Bead, 600 ohm @ 100 MHz, 3 A, 1210; Manufacturer: Taiyo Yuden; ZTyp@100MHz_Ohm: 600; SizeAreaWB_mm2: 14.7; DCR_ohm: 0.042; Value1: 0.042 ohm; Value: 600 ohm; Imax_A: 3A; SizeZ_mm: 2.8; SizeX_mm: 3.2; SizeY_mm: 2.5; SizeArea_mm2: 8
L2 = CMP-0086569-1: WE-MAIA SMD Power Inductor; Manufacturer: Wurth Electronics; DCR_ohm: 0.08; AEC Qualified: Yes; SizeZ_mm: 2mm; Irms: 2.4A; Material: Iron Powder; Isat: 4.3A; Symbol Name: SYM-78438336022; AEC Grade: Grade 1
L3 = CMP-0076872-1: Coupled inductor, 11 µH, 2.5 A, 0.03 ohm, SMD; Manufacturer: Wurth Elektronik; AEC Category: Q200; Value: 11uH; Ind_H: 11µH; DCR_ohm: 0.03
L4 = CMP-0059974-1: Inductor, 3.3 uH, 2 A, 0.127 ohm, SMD; Manufacturer: Cyntec; Isat: 2.5A @ 30% inductance drop; Irms: 2A @ 40C rise; SizeAreaWB_mm2: 14.7; DCR_ohm: 0.127; Value: 3.3uH; Imax_A: 2A; SizeZ_mm: 1.2; SizeX_mm: 3.2; SizeY_mm: 2.5; SizeArea_mm2: 8; Ind_H: 3.3µH; AEC Qualified: N; AEC Category: Q200
NT1-NT3 = CMP-0078142-1: Single point connection between nets.
R1 = CMP-0022717-2: RES, 0.51, 1%, 0.1 W, AEC-Q200 Grade 1, 0603; Manufacturer: Panasonic; PartNumber: ERJ-3RQFR51V; Power_W: 100mW; TempCo: 300 ppm/C; Value_Code: R510; U/M: EA; Value: 0.51; EIA_Code: E96; Res_ohm: 5.1d; SizeX_mm: 1.6; SizeY_mm: 0.8; SizeZ_mm: 1; Value2: 0.1W; SizeArea_mm2: 1.28; CompType: Resistor; AEC Qualified: Y; AEC Category: Q200
R2 = CMP-0020720-3: as R8 on sheet PMP22030_3V3
R3 R5 = CMP-0081856-1: as R9 on sheet PMP22030_3V3
R4 R6 R7 = CMP-0026753-1: as R10 on sheet PMP22030_3V3
U1 = CMP-0750138-1: 3.5-V to 36-V, 1.5-A Synchronous Step-Down Voltage Regulator with Spread Spectrum, PWP0016K (HTSSOP-16); Alternate Manufacturer: Texas Instruments; SizeX_mm: 6.4; SizeY_mm: 5; SizeZ_mm: 1.2; SizeAreaWB_mm2: 58.8; CompType: IC; AEC Category: Q200; AEC Qualified: Y; SizeArea_mm2: 32
U2 = CMP-0860155-1: Automotive capacitor-free 300-mA LDO regulator with foldback current limit for portable devices, DBV0005A (SOT-23-5); Manufacturer: Texas Instruments; SizeAreaWB_mm2: 14.82; SizeArea_mm2: 8.12; SizeY_mm: 2.9; CompType: IC; SizeZ_mm: 1.45; SizeX_mm: 2.8; AEC Category: Q200; AEC Qualified: Y

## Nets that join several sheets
GND: PMP22030_3V3 (42 pins), PMP22030_5V (30 pins)
VIN: PMP22030_3V3 (7 pins), PMP22030_5V (10 pins)

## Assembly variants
001: not fitted C10 C20 FID1 FID2 FID3 R2 R8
